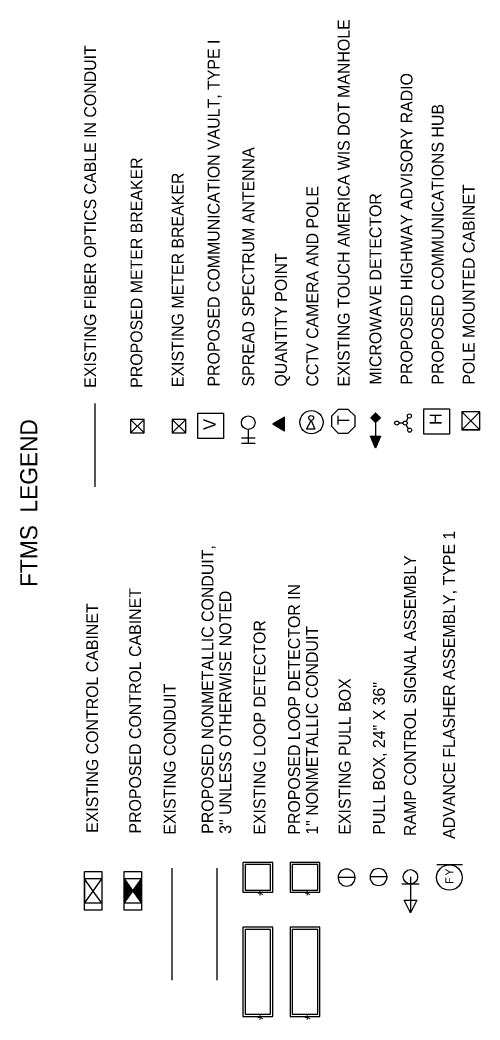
# Model space of a CAD drawing. Extents: x 584850 to 602551, y 145475 to 158627.
# Drawn here: x 602334.8 to 602551.3, y 145474.9 to 145946.2 of the extents above; entities that cross this region are included whole.
import ezdxf

# ---------------------------------------------------------------- set-up
doc = ezdxf.new("R2010")
doc.units = 0
for name, color, linetype in [('B_CONC_HIDDEN', 7, 'Continuous'), ('E_RDWY_BarrierConc', 7, 'Continuous'), ('P_PM', 7, 'Continuous'), ('P_PM_1RMTemp_50_50', 7, 'Continuous'), ('P_TC_WorkArea', 7, 'Continuous')]:
    doc.layers.add(name, color=color, linetype=linetype)

msp = doc.modelspace()

# ---------------------------------------------------------------- linework, layer by layer
at = {"layer": 'B_CONC_HIDDEN'}
for p, q in [((602370.16, 145726.25), (602370.16, 145765.43)), ((602412.88, 145758.01), (602406.48, 145751.61)), ((602412.88, 145751.61), (602406.48, 145758.01)), ((602406.45, 145493.74), (602406.45, 145546.52)), ((602453.74, 145549.18), (602439.74, 145549.18)), ((602439.74, 145549.18), (602439.74, 145535.18)), ((602452.74, 145548.18), (602440.74, 145548.18)), ((602440.74, 145548.18), (602440.74, 145536.18)), ((602452.74, 145536.18), (602452.74, 145548.18)), ((602453.74, 145535.18), (602453.74, 145549.18)), ((602365.1, 145526.62), (602365.1, 145544.95)), ((602365.1, 145544.95), (602373.26, 145544.95)), ((602373.26, 145541.45), (602365.1, 145541.45)), ((602373.26, 145544.95), (602373.26, 145526.62)), ((602492.56, 145542.05), (602484.56, 145542.06)), ((602492.56, 145541.9), (602492.56, 145542.06)), ((602440.74, 145536.18), (602446.74, 145536.17)), ((602446.74, 145536.17), (602452.74, 145536.18)), ((602439.74, 145535.68), (602439.96, 145535.68)), ((602439.74, 145535.18), (602453.74, 145535.18)), ((602453.74, 145535.68), (602453.52, 145535.68)), ((602373.26, 145529.93), (602365.1, 145529.93)), ((602373.26, 145526.62), (602365.1, 145526.62)), ((602453.74, 145518.62), (602439.74, 145518.63)), ((602439.74, 145518.63), (602439.74, 145476.63)), ((602452.74, 145517.62), (602440.74, 145517.63)), ((602440.74, 145517.63), (602440.74, 145477.63)), ((602452.74, 145477.62), (602452.74, 145517.62)), ((602453.74, 145476.62), (602453.74, 145518.62)), ((602439.74, 145477.12), (602439.96, 145477.13)), ((602439.74, 145476.63), (602453.74, 145476.62)), ((602440.74, 145477.63), (602446.74, 145477.63)), ((602446.74, 145477.63), (602452.74, 145477.62)), ((602453.74, 145477.13), (602453.52, 145477.12))]:
    msp.add_line(p, q, dxfattribs=at)
for points in [[(602489.29, 145762.72), (602484.65, 145762.72), (602481.37, 145759.44), (602481.37, 145754.8), (602484.65, 145751.52), (602489.29, 145751.52), (602492.57, 145754.8), (602492.57, 145759.44)], [(602412.88, 145758.01), (602406.48, 145758.01), (602406.48, 145751.61), (602412.88, 145751.61)], [(602365.1, 145529.93), (602369.18, 145535.69), (602365.1, 145541.45)], [(602373.26, 145529.93), (602369.18, 145535.69), (602373.26, 145541.45)]]:
    msp.add_lwpolyline(points, close=True, dxfattribs=at)
for start, end in [(0, 180), (180, 180.0855), (181.3904, 357.7675), (359.4927, 0)]:
    msp.add_arc((602488.56, 145542.05), 4, start, end, dxfattribs=at)
at = {"layer": 'E_RDWY_BarrierConc'}
for p, q in [((602393.27, 145758.01), (602386.87, 145751.61)), ((602393.27, 145751.61), (602386.87, 145758.01)), ((602456.73, 145757.56), (602454.57, 145755.4)), ((602457.37, 145757.93), (602454.74, 145755.3)), ((602458.01, 145758.3), (602454.92, 145755.2)), ((602458.65, 145758.67), (602455.09, 145755.1)), ((602459.3, 145759.04), (602455.26, 145755.01)), ((602459.3, 145758.77), (602455.43, 145754.91)), ((602459.3, 145758.5), (602455.6, 145754.81)), ((602459.3, 145758.23), (602455.78, 145754.71)), ((602459.3, 145757.96), (602455.95, 145754.61)), ((602459.3, 145757.69), (602456.12, 145754.51)), ((602456.89, 145757.65), (602459.3, 145755.24)), ((602457.06, 145757.75), (602459.3, 145755.51)), ((602457.23, 145757.85), (602459.3, 145755.78)), ((602457.4, 145757.95), (602459.3, 145756.06)), ((602457.58, 145758.05), (602459.3, 145756.33)), ((602457.75, 145758.15), (602459.3, 145756.6)), ((602457.92, 145758.25), (602459.3, 145756.87)), ((602458.09, 145758.35), (602459.3, 145757.14)), ((602458.26, 145758.45), (602459.3, 145757.41)), ((602458.44, 145758.55), (602459.3, 145757.69)), ((602458.61, 145758.65), (602459.3, 145757.96)), ((602458.78, 145758.74), (602459.3, 145758.23)), ((602458.95, 145758.84), (602459.3, 145758.5)), ((602459.12, 145758.94), (602459.3, 145758.77)), ((602504.44, 145758.74), (602499.91, 145758.74)), ((602500.02, 145758.85), (602500.02, 145758.63)), ((602504.25, 145758.93), (602500.1, 145758.93)), ((602504.25, 145758.55), (602500.1, 145758.55)), ((602500.21, 145759.04), (602500.21, 145758.44)), ((602504.05, 145759.12), (602500.3, 145759.12)), ((602504.05, 145758.35), (602500.3, 145758.35)), ((602500.41, 145759.23), (602500.41, 145758.24)), ((602503.86, 145759.31), (602500.49, 145759.31)), ((602503.86, 145758.16), (602500.49, 145758.16)), ((602500.6, 145759.42), (602500.6, 145758.05)), ((602503.67, 145759.51), (602500.68, 145759.51)), ((602503.67, 145757.97), (602500.68, 145757.97)), ((602500.79, 145759.61), (602500.79, 145757.86)), ((602503.48, 145759.7), (602500.87, 145759.7)), ((602503.48, 145757.78), (602500.87, 145757.78)), ((602500.98, 145759.81), (602500.98, 145757.67)), ((602503.29, 145759.89), (602501.06, 145759.89)), ((602503.29, 145757.59), (602501.06, 145757.59)), ((602501.17, 145760), (602501.17, 145757.48)), ((602503.09, 145760.08), (602501.26, 145760.08)), ((602501.37, 145760.19), (602501.37, 145757.28)), ((602502.9, 145760.27), (602501.45, 145760.27)), ((602501.56, 145760.38), (602501.56, 145757.09)), ((602502.71, 145760.47), (602501.64, 145760.47)), ((602501.75, 145760.57), (602501.75, 145756.9)), ((602502.52, 145760.66), (602501.83, 145760.66)), ((602501.94, 145760.77), (602501.94, 145756.71)), ((602502.33, 145760.85), (602502.02, 145760.85)), ((602502.13, 145760.96), (602502.13, 145756.52)), ((602502.33, 145760.85), (602502.33, 145756.63)), ((602502.52, 145760.66), (602502.52, 145756.82)), ((602502.71, 145760.47), (602502.71, 145757.01)), ((602502.9, 145760.27), (602502.9, 145757.2)), ((602503.09, 145760.08), (602503.09, 145757.39)), ((602503.29, 145759.89), (602503.29, 145757.59)), ((602503.48, 145759.7), (602503.48, 145757.78)), ((602503.67, 145759.51), (602503.67, 145757.97)), ((602503.86, 145759.31), (602503.86, 145758.16)), ((602504.05, 145759.12), (602504.05, 145758.35)), ((602504.25, 145758.93), (602504.25, 145758.55)), ((602517.59, 145758.83), (602516.59, 145757.09)), ((602551.34, 145761.62), (602542.82, 145753.1)), ((602551.34, 145753.1), (602542.82, 145761.62)), ((602442.24, 145753.26), (602442.24, 145746.86)), ((602454.16, 145756.07), (602453.88, 145755.8)), ((602453.96, 145755.96), (602454.45, 145755.47)), ((602454.8, 145756.45), (602454.05, 145755.7)), ((602454.13, 145756.06), (602455.09, 145755.1)), ((602455.44, 145756.82), (602454.23, 145755.6)), ((602454.31, 145756.16), (602455.74, 145754.73)), ((602456.08, 145757.19), (602454.4, 145755.5)), ((602454.48, 145756.26), (602456.38, 145754.36)), ((602454.65, 145756.36), (602457.02, 145753.99)), ((602454.82, 145756.46), (602457.66, 145753.62)), ((602454.99, 145756.56), (602458.31, 145753.24)), ((602455.17, 145756.66), (602458.95, 145752.87)), ((602455.34, 145756.76), (602459.3, 145752.8)), ((602455.51, 145756.86), (602459.3, 145753.07)), ((602455.68, 145756.96), (602459.3, 145753.34)), ((602455.85, 145757.05), (602459.3, 145753.61)), ((602456.03, 145757.15), (602459.3, 145753.88)), ((602456.2, 145757.25), (602459.3, 145754.16)), ((602459.3, 145757.41), (602456.29, 145754.41)), ((602456.37, 145757.35), (602459.3, 145754.43)), ((602459.3, 145757.14), (602456.46, 145754.31)), ((602456.54, 145757.45), (602459.3, 145754.7)), ((602459.3, 145756.87), (602456.64, 145754.21)), ((602456.72, 145757.55), (602459.3, 145754.97)), ((602459.3, 145756.6), (602456.81, 145754.11)), ((602459.3, 145756.33), (602456.98, 145754.01)), ((602459.3, 145756.06), (602457.15, 145753.91)), ((602459.3, 145755.78), (602457.32, 145753.81)), ((602459.3, 145755.51), (602457.5, 145753.71)), ((602459.3, 145755.24), (602457.67, 145753.61)), ((602459.3, 145754.97), (602457.84, 145753.51)), ((602459.3, 145754.7), (602458.01, 145753.41)), ((602459.3, 145754.43), (602458.19, 145753.32)), ((602459.3, 145754.16), (602458.36, 145753.22)), ((602459.3, 145753.88), (602458.53, 145753.12)), ((602459.3, 145753.61), (602458.7, 145753.02)), ((602459.3, 145753.34), (602458.87, 145752.92)), ((602459.3, 145753.07), (602459.05, 145752.82)), ((602503.09, 145757.39), (602501.26, 145757.39)), ((602502.9, 145757.2), (602501.45, 145757.2)), ((602502.71, 145757.01), (602501.64, 145757.01)), ((602502.52, 145756.82), (602501.83, 145756.82)), ((602502.33, 145756.63), (602502.02, 145756.63)), ((602502.18, 145756.47), (602502.18, 145750.1)), ((602515.16, 145756.27), (602513.16, 145756.27)), ((602517.59, 145753.7), (602516.59, 145755.44)), ((602439.04, 145749.26), (602445.44, 145749.26)), ((602442.24, 145749.44), (602442.24, 145749.65)), ((602442.24, 145749.44), (602442.24, 145749.65)), ((602442.24, 145749.44), (602442.24, 145749.44)), ((602442.24, 145749.44), (602442.24, 145749.44)), ((602459.3, 145752.8), (602459.22, 145752.72)), ((602499.86, 145750.1), (602499.8, 145750.05)), ((602503.11, 145746.68), (602499.84, 145749.95)), ((602500.14, 145750.1), (602499.89, 145749.85)), ((602503.19, 145746.88), (602499.97, 145750.1)), ((602500.42, 145750.1), (602499.97, 145749.65)), ((602500.71, 145750.1), (602500.05, 145749.45)), ((602503.02, 145746.48), (602500.05, 145749.45)), ((602500.99, 145750.1), (602500.14, 145749.25)), ((602501.27, 145750.1), (602500.22, 145749.06)), ((602503.28, 145747.08), (602500.25, 145750.1)), ((602502.94, 145746.28), (602500.27, 145748.96)), ((602501.55, 145750.1), (602500.31, 145748.86)), ((602501.84, 145750.1), (602500.39, 145748.66)), ((602502.12, 145750.1), (602500.48, 145748.46)), ((602502.85, 145746.09), (602500.48, 145748.46)), ((602503.36, 145747.27), (602500.54, 145750.1)), ((602502.4, 145750.1), (602500.56, 145748.26)), ((602502.68, 145750.1), (602500.65, 145748.07)), ((602502.97, 145750.1), (602500.73, 145747.87)), ((602503.45, 145747.47), (602500.82, 145750.1)), ((602503.25, 145750.1), (602500.82, 145747.67)), ((602503.53, 145750.1), (602500.9, 145747.47)), ((602503.82, 145750.1), (602500.99, 145747.27)), ((602504.1, 145750.1), (602501.07, 145747.08)), ((602503.53, 145747.67), (602501.1, 145750.1)), ((602504.38, 145750.1), (602501.16, 145746.88)), ((602504.51, 145749.95), (602501.24, 145746.68)), ((602504.3, 145749.45), (602501.33, 145746.48)), ((602503.62, 145747.87), (602501.38, 145750.1)), ((602504.09, 145748.96), (602501.41, 145746.28)), ((602503.87, 145748.46), (602501.5, 145746.09)), ((602503.7, 145748.07), (602501.67, 145750.1)), ((602503.79, 145748.26), (602501.95, 145750.1)), ((602503.87, 145748.46), (602502.23, 145750.1)), ((602503.96, 145748.66), (602502.52, 145750.1)), ((602504.04, 145748.86), (602502.8, 145750.1)), ((602504.13, 145749.06), (602503.08, 145750.1)), ((602504.21, 145749.25), (602503.36, 145750.1)), ((602504.3, 145749.45), (602503.65, 145750.1)), ((602504.38, 145749.65), (602503.93, 145750.1)), ((602504.47, 145749.85), (602504.21, 145750.1)), ((602504.55, 145750.05), (602504.5, 145750.1)), ((602439.04, 145746.86), (602445.44, 145746.86)), ((602502.77, 145745.89), (602500.69, 145747.97)), ((602502.69, 145745.69), (602500.9, 145747.47)), ((602502.6, 145745.49), (602501.12, 145746.98)), ((602502.52, 145745.29), (602501.33, 145746.48)), ((602502.43, 145745.1), (602501.54, 145745.99)), ((602503.66, 145747.97), (602501.58, 145745.89)), ((602503.45, 145747.47), (602501.67, 145745.69)), ((602503.24, 145746.98), (602501.75, 145745.49)), ((602502.35, 145744.9), (602501.75, 145745.49)), ((602503.02, 145746.48), (602501.84, 145745.29)), ((602502.81, 145745.99), (602501.92, 145745.1)), ((602502.26, 145744.7), (602501.96, 145745)), ((602502.6, 145745.49), (602502.01, 145744.9)), ((602502.39, 145745), (602502.09, 145744.7)), ((602502.18, 145744.5), (602502.18, 145744.5)), ((602537.02, 145548.13), (602530.97, 145548.13)), ((602543.07, 145548.13), (602537.02, 145548.13)), ((602383.82, 145526.62), (602383.82, 145544.95)), ((602383.82, 145544.95), (602391.97, 145544.95)), ((602391.97, 145541.45), (602383.82, 145541.45)), ((602383.82, 145541.45), (602391.98, 145529.93)), ((602383.82, 145529.93), (602391.98, 145541.45)), ((602384.09, 145541.07), (602383.82, 145541.07)), ((602391.71, 145541.07), (602391.98, 145541.07)), ((602391.97, 145544.95), (602391.97, 145526.62)), ((602384.44, 145540.57), (602383.82, 145540.57)), ((602384.8, 145540.07), (602383.82, 145540.07)), ((602385.15, 145539.57), (602383.82, 145539.57)), ((602385.5, 145539.07), (602383.82, 145539.07)), ((602385.86, 145538.57), (602383.82, 145538.57)), ((602386.21, 145538.07), (602383.82, 145538.07)), ((602386.57, 145537.57), (602383.82, 145537.57)), ((602386.92, 145537.07), (602383.82, 145537.07)), ((602387.27, 145536.57), (602383.82, 145536.57)), ((602387.63, 145536.07), (602383.82, 145536.07)), ((602388.17, 145536.07), (602391.98, 145536.07)), ((602388.53, 145536.57), (602391.98, 145536.57)), ((602388.88, 145537.07), (602391.98, 145537.07)), ((602389.23, 145537.57), (602391.98, 145537.57)), ((602389.59, 145538.07), (602391.98, 145538.07)), ((602389.94, 145538.57), (602391.98, 145538.57)), ((602390.3, 145539.07), (602391.98, 145539.07)), ((602390.65, 145539.57), (602391.98, 145539.57)), ((602391.01, 145540.07), (602391.98, 145540.07)), ((602391.36, 145540.57), (602391.98, 145540.57)), ((602387.82, 145535.57), (602383.82, 145535.57)), ((602387.46, 145535.07), (602383.82, 145535.07)), ((602387.11, 145534.57), (602383.82, 145534.57)), ((602386.76, 145534.07), (602383.82, 145534.07)), ((602386.4, 145533.57), (602383.82, 145533.57)), ((602386.05, 145533.07), (602383.82, 145533.07)), ((602385.69, 145532.57), (602383.82, 145532.57)), ((602385.34, 145532.07), (602383.82, 145532.07)), ((602384.98, 145531.57), (602383.82, 145531.57)), ((602387.98, 145535.57), (602391.98, 145535.57)), ((602388.34, 145535.07), (602391.98, 145535.07)), ((602388.69, 145534.57), (602391.98, 145534.57)), ((602389.05, 145534.07), (602391.98, 145534.07)), ((602389.4, 145533.57), (602391.98, 145533.57)), ((602389.75, 145533.07), (602391.98, 145533.07)), ((602390.11, 145532.57), (602391.98, 145532.57)), ((602390.46, 145532.07), (602391.98, 145532.07)), ((602390.82, 145531.57), (602391.98, 145531.57)), ((602518.61, 145525.42), (602515.6, 145531.42)), ((602515.6, 145531.42), (602521.61, 145531.42)), ((602521.61, 145531.42), (602518.61, 145525.42)), ((602384.63, 145531.07), (602383.82, 145531.07)), ((602384.28, 145530.57), (602383.82, 145530.57)), ((602383.92, 145530.07), (602383.82, 145530.07)), ((602391.97, 145529.93), (602383.82, 145529.93)), ((602391.17, 145531.07), (602391.98, 145531.07)), ((602391.52, 145530.57), (602391.98, 145530.57)), ((602391.88, 145530.07), (602391.98, 145530.07)), ((602391.97, 145526.62), (602383.82, 145526.62))]:
    msp.add_line(p, q, dxfattribs=at)
for points in [[(602393.27, 145758.01), (602386.87, 145758.01), (602386.87, 145751.61), (602393.27, 145751.61)], [(602418.52, 145748.94), (602418.52, 145760.94), (602430.52, 145760.94), (602430.52, 145748.94)], [(602459.3, 145752.67), (602459.3, 145759.04), (602453.78, 145755.86)], [(602502.18, 145756.47), (602499.91, 145758.74), (602502.18, 145761), (602504.44, 145758.74)], [(602551.34, 145761.62), (602542.82, 145761.62), (602542.82, 145753.1), (602551.34, 145753.1)], [(602542.82, 145761.62), (602547.08, 145757.36), (602551.34, 145761.62)], [(602469.72, 145753.38), (602471.88, 145757.54), (602473.59, 145753.4)], [(602542.82, 145753.11), (602547.08, 145757.36), (602551.34, 145753.11)], [(602504.58, 145750.1), (602502.18, 145744.5), (602499.78, 145750.1)], [(602383.82, 145529.93), (602387.9, 145535.69), (602383.82, 145541.45)]]:
    msp.add_lwpolyline(points, close=True, dxfattribs=at)
for centre, radius in [((602442.24, 145756.46), 3.2), ((602442.24, 145756.46), 3.2), ((602472.01, 145756.65), 5.46), ((602471.88, 145758.68), 1.14), ((602518.1, 145759.6), 0.954), ((602512.2, 145756.27), 0.954), ((602516.11, 145756.27), 0.954), ((602518.2, 145752.92), 0.954), ((602536.95, 145542.1), 6)]:
    msp.add_circle(centre, radius, dxfattribs=at)
at = {"layer": 'P_PM'}
for p, q in [((602518.61, 145542.42), (602518.61, 145525.42)), ((602514.57, 145539.06), (602518.6, 145539.06)), ((602518.6, 145539.06), (602522.64, 145539.06)), ((602518.6, 145539.06), (602522.64, 145539.06)), ((602518.69, 145539.06), (602522.72, 145539.06)), ((602518.61, 145525.42), (602515.6, 145531.42)), ((602515.6, 145531.42), (602521.61, 145531.42)), ((602521.61, 145531.42), (602518.61, 145525.42))]:
    msp.add_line(p, q, dxfattribs=at)
msp.add_circle((602518.6, 145542.42), 3.38, dxfattribs=at)
at = {"layer": 'P_TC_WorkArea'}
for p, q in [((602524.94, 145750.99), (602524.94, 145762.99)), ((602524.94, 145762.99), (602536.94, 145762.99)), ((602536.94, 145762.99), (602536.94, 145750.99)), ((602418.52, 145748.94), (602418.52, 145760.94)), ((602418.52, 145760.94), (602430.52, 145760.94)), ((602430.52, 145760.94), (602430.52, 145748.94)), ((602430.52, 145748.94), (602418.52, 145748.94)), ((602536.94, 145750.99), (602524.94, 145750.99)), ((602427.56, 145493.74), (602427.56, 145546.52)), ((602475.95, 145549.18), (602461.95, 145549.18)), ((602461.95, 145549.18), (602461.95, 145535.18)), ((602474.95, 145548.18), (602462.95, 145548.18)), ((602462.95, 145548.18), (602462.95, 145536.18)), ((602474.95, 145536.18), (602474.95, 145548.18)), ((602475.95, 145535.18), (602475.95, 145549.18)), ((602507.58, 145542.33), (602499.58, 145542.33)), ((602507.58, 145542.18), (602507.58, 145542.33)), ((602462.95, 145536.18), (602468.95, 145536.17)), ((602468.95, 145536.17), (602474.95, 145536.18)), ((602461.95, 145535.68), (602462.17, 145535.68)), ((602461.95, 145535.18), (602475.95, 145535.18)), ((602475.95, 145535.68), (602475.73, 145535.68)), ((602475.95, 145518.62), (602461.95, 145518.63)), ((602461.95, 145518.63), (602461.95, 145476.63)), ((602474.95, 145517.62), (602462.95, 145517.63)), ((602462.95, 145517.63), (602462.95, 145477.63)), ((602474.95, 145477.62), (602474.95, 145517.62)), ((602475.95, 145476.62), (602475.95, 145518.62)), ((602461.95, 145477.12), (602462.17, 145477.13)), ((602461.95, 145476.63), (602475.95, 145476.62)), ((602462.95, 145477.63), (602468.95, 145477.63)), ((602468.95, 145477.63), (602474.95, 145477.62)), ((602475.95, 145477.13), (602475.73, 145477.12))]:
    msp.add_line(p, q, dxfattribs=at)
for start, end in [(0, 180), (180, 180.0855), (181.3904, 357.7675), (359.4927, 0)]:
    msp.add_arc((602503.58, 145542.33), 4, start, end, dxfattribs=at)

# ---------------------------------------------------------------- texts
at = {"layer": 'B_CONC_HIDDEN'}
for s, height, p in [('T', 5.6, (602489.77, 145755.29)), ('*', 5.04, (602451.77, 145533.37)), ('*', 5.04, (602451.77, 145474.82))]:
    msp.add_text(s, height=height, rotation=90, dxfattribs=at).set_placement(p)
at = {"layer": 'E_RDWY_BarrierConc'}
for s, p in [('Y', (602538.74, 145542.96)), ('F', (602538.81, 145539.11))]:
    msp.add_text(s, height=3.75, rotation=90, dxfattribs=at).set_placement(p)
at = {"layer": 'P_PM'}
msp.add_text('RAMP CONTROL SIGNAL ASSEMBLY', height=5.6, rotation=90, dxfattribs=at).set_placement((602521.17, 145561.6))
at = {"layer": 'P_PM_1RMTemp_50_50'}
for s, height, p in [('EXISTING TOUCH AMERICA WIS DOT MANHOLE', 5.6, (602489.98, 145773.47)), ('EXISTING FIBER OPTICS CABLE IN CONDUIT', 5.6, (602370.61, 145772.88)), ('PROPOSED COMMUNICATION VAULT, TYPE I', 5.6, (602428.74, 145773.47)), ('PROPOSED HIGHWAY ADVISORY RADIO', 5.6, (602519.57, 145774.33)), ('PROPOSED COMMUNICATIONS HUB', 5.6, (602534.21, 145774.33)), ('SPREAD SPECTRUM ANTENNA', 5.6, (602445.03, 145773.47)), ('PROPOSED METER BREAKER', 5.6, (602392.41, 145772.88)), ('EXISTING METER BREAKER', 5.6, (602411.8, 145773.18)), ('CCTV CAMERA AND POLE', 5.6, (602475.2, 145773.47)), ('POLE MOUNTED CABINET', 5.6, (602548.85, 145774.33)), ('MICROWAVE DETECTOR', 5.6, (602504.93, 145774.33)), ('QUANTITY POINT', 5.6, (602460.41, 145773.47)), ('FTMS  LEGEND', 8, (602342.91, 145679.05)), ('ADVANCE FLASHER ASSEMBLY, TYPE 1', 5.6, (602539.54, 145560.27)), ('PROPOSED NONMETALLIC CONDUIT,', 5.6, (602425.87, 145562.66)), ('PROPOSED CONTROL CABINET', 5.6, (602391.78, 145562.81)), ('PROPOSED LOOP DETECTOR IN ', 5.6, (602466.62, 145562.28)), ('3" UNLESS OTHERWISE NOTED', 5.6, (602434.27, 145562.66)), ('EXISTING CONTROL CABINET', 5.6, (602371.55, 145563.1)), ('EXISTING LOOP DETECTOR', 5.6, (602450.35, 145562.28)), ('1" NONMETALLIC CONDUIT', 5.6, (602475.02, 145562.28)), ('EXISTING PULL BOX', 5.6, (602490.48, 145562.28)), ('EXISTING CONDUIT', 5.6, (602408.06, 145562.28)), ('PULL BOX, 24" X 36"', 5.6, (602506.57, 145562.28))]:
    msp.add_text(s, height=height, rotation=90, dxfattribs=at).set_placement(p)
at = {"layer": 'P_TC_WorkArea'}
for s, height, p in [('V', 5.76, (602426.93, 145753.05)), ('H', 5.76, (602533.36, 145755.34)), ('*', 5.04, (602473.98, 145533.37)), ('*', 5.04, (602473.98, 145474.82))]:
    msp.add_text(s, height=height, rotation=90, dxfattribs=at).set_placement(p)

doc.saveas('drawing.dxf')
